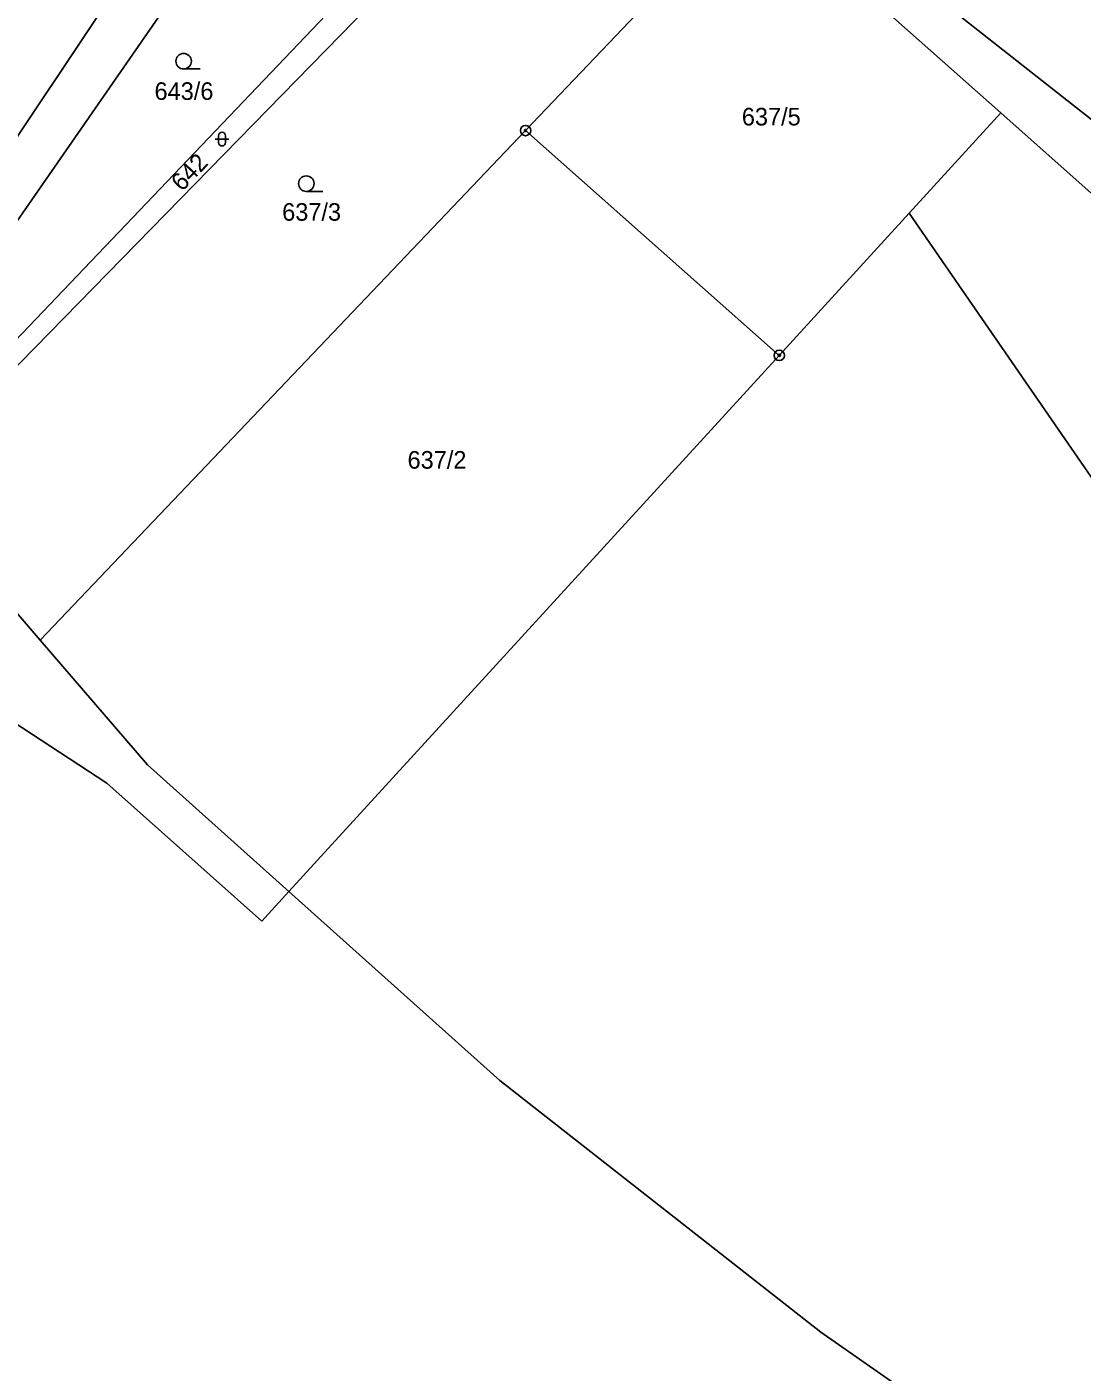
# Model space of a CAD drawing. Extents: x -547623 to -538651, y -1096714 to -1086522.
# Drawn here: x -542450.9 to -542349, y -1093102.4 to -1092972.4 of the extents above; entities that cross this region are included whole.
import ezdxf

# ---------------------------------------------------------------- set-up
doc = ezdxf.new("R2010")
doc.units = 0
for name, color, linetype in [('Vrstva 1', 7, 'Continuous'), ('Vrstva 25', 7, 'Continuous'), ('Vrstva 83', 7, 'Continuous'), ('Vrstva 86', 7, 'Continuous')]:
    doc.layers.add(name, color=color, linetype=linetype)

msp = doc.modelspace()

# ---------------------------------------------------------------- linework, layer by layer
at = {"layer": 'Vrstva 1'}
for points in [[(-542408.03, -1092960.23), (-542462.85, -1093016.3)], [(-542402.78, -1092982.39), (-542381.38, -1092959.91)], [(-542372.8, -1092961.85), (-542333.91, -1092992.5)], [(-542463.47, -1093014.64), (-542414.71, -1092963.49)], [(-542441.78, -1092967.83), (-542455.55, -1092988.45)], [(-542436.57, -1092969), (-542466.67, -1093012.42)], [(-542356.88, -1092980.68), (-542369.28, -1092969.65)], [(-542356.88, -1092980.68), (-542365.74, -1092990.38)], [(-542323.13, -1093010.72), (-542356.88, -1092980.68)], [(-542449.67, -1093031.64), (-542402.78, -1092982.39)], [(-542402.78, -1092982.39), (-542378.27, -1093004.12)], [(-542365.74, -1092990.38), (-542378.27, -1093004.12)], [(-542296.98, -1093090.1), (-542365.74, -1092990.38)], [(-542425.66, -1093055.94), (-542378.27, -1093004.12)], [(-542462.85, -1093016.3), (-542449.67, -1093031.64)], [(-542449.67, -1093031.64), (-542439.3, -1093043.71)], [(-542463.21, -1093032.4), (-542443.24, -1093045.46)], [(-542439.3, -1093043.71), (-542425.66, -1093055.94)], [(-542443.24, -1093045.46), (-542428.27, -1093058.79)], [(-542428.27, -1093058.79), (-542425.66, -1093055.94)], [(-542425.66, -1093055.94), (-542405.28, -1093074.2)], [(-542405.28, -1093074.2), (-542374.27, -1093098.54)], [(-542374.27, -1093098.54), (-542322.4, -1093134.78)]]:
    msp.add_lwpolyline(points, dxfattribs=at)
at = {"layer": 'Vrstva 25'}
for p, q in [((-542435.81, -1092976.44), (-542434.21, -1092976.44)), ((-542432.77, -1092983.22), (-542431.43, -1092983.22)), ((-542432.44, -1092983.55), (-542432.44, -1092982.89)), ((-542431.77, -1092982.89), (-542431.77, -1092983.55)), ((-542423.96, -1092988.27), (-542422.36, -1092988.27))]:
    msp.add_line(p, q, dxfattribs=at)
for centre in [(-542435.81, -1092975.69), (-542423.96, -1092987.52)]:
    msp.add_circle(centre, 0.75, dxfattribs=at)
for centre, start, end in [((-542432.1, -1092982.89), 0, 180), ((-542432.1, -1092983.55), 180, 0)]:
    msp.add_arc(centre, 0.335, start, end, dxfattribs=at)
at = {"layer": 'Vrstva 83'}
for centre, radius in [((-542402.78, -1092982.39), 0.5), ((-542402.78, -1092982.39), 0.1), ((-542378.27, -1093004.12), 0.5), ((-542378.27, -1093004.12), 0.1)]:
    msp.add_circle(centre, radius, dxfattribs=at)

# ---------------------------------------------------------------- texts
at = {"layer": 'Vrstva 86'}
for s, p in [('643/6', (-542438.62, -1092979.43)), ('637/5', (-542381.89, -1092981.9)), ('637/3', (-542426.29, -1092991.11)), ('637/2', (-542414.18, -1093015.07))]:
    msp.add_text(s, height=1.7, dxfattribs=at).set_placement(p)
msp.add_text('642', height=1.7, rotation=46.14, dxfattribs=at).set_placement((-542435.96, -1092988.35))

doc.saveas('drawing.dxf')
